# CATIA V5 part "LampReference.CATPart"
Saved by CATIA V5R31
Part number: LampReference
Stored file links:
  C:\Users\patol451\OneDrive - Linköpings universitet\Nuvarande kurser\Exjobb\LampCATIA\LampReference.CATPart

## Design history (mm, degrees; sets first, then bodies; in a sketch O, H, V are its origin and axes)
Parameters
  group "BaseParameters"
    baseWidth = 100 mm
    baseDepth = 100 mm
    baseHeight = 10 mm
    lampSwivelAngle = 0 deg
    baseConnectionHeight = 20 mm
  group "LowerSupportParameters"
    lowerConnectionWidth = 30 mm
    upperConnectionWidth = 30 mm
    lowerSupportHeight = 100 mm
    lowerAxleAngle = 0 deg
  group "UpperSupportParameters"
    upperSupportHeight = 100 mm
    upperAxleAngle = 0 deg
  group "HeadSupportParameters"
    headSupportWidth = 50 mm
    headSupportHeight = 40 mm
    headSupportAngle = 0 deg
  group "LampHeadParameters"
    lampHeadAngle = 0 deg
AxisSystem1 "Origin": origin (0, 0, 0), X (1, 0, 0), Y (0, 1, 0), Z (0, 0, 1)
Set1 "Base"
  Point1 "Origin": type OnPlane, Support xy-plane, H 0, V 0, Direction (1, 0, 0)
  Point2 "P1": type OnPlane, Support xy-plane, H 0, V 50 {= baseDepth  /2}, Direction (1, 0, 0)
  Point3 "P2": type OnPlane, Support xy-plane, H 50 {= baseWidth  /2}, V 0, Direction (1, 0, 0)
  Symmetry1 "P3": ToTransfor Point2, Reference zx-plane
  Symmetry2 "P4": ToTransfor Point3, Reference yz-plane
  Curve1 "BaseEllipse": Elements (Symmetry2; Point2; Point3; Symmetry1), SemiClosure Point3
  Plane1 "BaseHeightPlane": type Offset, RefPlane xy-plane, Offset 10 {= baseHeight}
  Point4 "BaseConnectionPoint_1": type OnPlane, Support Plane1, H 0, V 0, Direction (1, 0, 0)
  Translate1 "BaseTopAxisSystem": ToTransfor AxisSystem1, FirstPoint Point1, SecondPoint Point4
  Rotate1 "LampSwivelAxisSystem": ToTransfor Translate1, Axis edge [face of Translate1 | face of Translate1], Angle 0 {= lampSwivelAngle}
  Plane2 "BaseConnectionHeightPlane": type Offset, RefPlane face of Rotate1, Offset 20 {= baseConnectionHeight}
  Point5 "P1_Box": (50 {= baseWidth /2}, 50 {= baseDepth /2}, 0), relative to Point1
  Point6 "P2_Box": (50 {= baseWidth /2}, -50 {= -baseDepth /2}, 0), relative to Point1
  Point7 "P3_Box": (-50 {= -baseWidth /2}, -50 {= -baseDepth /2}, 0), relative to Point1
  Point8 "P4_Box": (-50 {= -baseWidth /2}, 50 {= baseDepth /2}, 0), relative to Point1
Set2 "LowerSupport"
  Point9 "BaseConnectionPoint_2": type OnPlane, Support Plane2, H 0, V 0, Direction (1, 0, 0)
  Point10 "LowerAxlePointRight": (15 {= lowerConnectionWidth  /2}, 0, 20 {= baseConnectionHeight}), in Rotate1
  Symmetry3 "LowerAxlePointLeft": ToTransfor Point10, Reference face of Rotate1
  Translate2 "IntermediaryAxisSystem": ToTransfor Rotate1, FirstPoint Point4, SecondPoint Point9
  Rotate2 "MiddleAxisSystem_2": ToTransfor Translate2, Axis edge [face of Translate2 | face of Translate2], Angle 0 {= lowerAxleAngle}
  Plane3: type Offset, RefPlane face of Rotate2, Offset 0
  Plane4 "PlaneHeight_2": type Offset, RefPlane Plane3, Offset 100 {= lowerSupportHeight}
Set3 "UpperSupport"
  Point11 "UpperAxlePointRight": (15 {= upperConnectionWidth  /2}, 0, 100 {= lowerSupportHeight}), relative to Point9, in Rotate2
  Symmetry4 "UpperAxlePointLeft": ToTransfor Point11, Reference face of Rotate2
  Translate3: ToTransfor Rotate2, FirstPoint Point9, SecondPoint Project1
  Rotate3: ToTransfor Translate3, Axis edge [face of Translate3 | face of Translate3], Angle 0 {= upperAxleAngle}
  Plane5: type Offset, RefPlane face of Rotate3, Offset 0
  Plane6: type Offset, RefPlane Plane5, Offset 100 {= upperSupportHeight}
  Project1 "UpperSupportRodPoint_1": ToProject Point9, Support Plane4
  Project2 "UpperSupportRodPoint_2": ToProject Project1, Support {inverselocal InverseElem Plane6}
Set4 "HeadSupport"
  Translate4: ToTransfor Rotate3, FirstPoint Project1, SecondPoint Project2
  Rotate4: ToTransfor Translate4, Axis edge [face of Translate4 | face of Translate4], Angle 0 {= headSupportAngle}
  Plane7: type Offset, RefPlane face of Rotate4, Offset 0
  Plane8 "xy": type Offset, RefPlane face of Rotate4, Offset 0
  Plane9: type Offset, RefPlane Plane8, Offset 40 {= headSupportHeight}
  Project3 "HeadSupportPointMiddle": ToProject Project2, Support Plane9
  Point12 "HeadSupportPointRight": (25 {= headSupportWidth  /2}, 0, 0), relative to Project3, in Rotate4
  Symmetry5 "HeadSupportPointLeft": ToTransfor Point12, Reference Plane7
Set5 "LampHead"
  Translate5: ToTransfor Rotate4, FirstPoint Project2, SecondPoint Project3
  Rotate5 "LampHeadAxisSystem": ToTransfor Translate5, Axis edge [face of Translate5 | face of Translate5], Angle 0 {= lampHeadAngle}
  Plane10 "xy": type Offset, RefPlane face of Rotate5, Offset 0
  Plane11 "yz": type Offset, RefPlane face of Rotate5, Offset 0
  Plane12 "zx": type Offset, RefPlane face of Rotate5, Offset 0
  Rotate6 "P1": ToTransfor Project2, Axis edge [face of Rotate5 | face of Rotate5], Angle 0 {= lampHeadAngle}
Body1 (main body)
